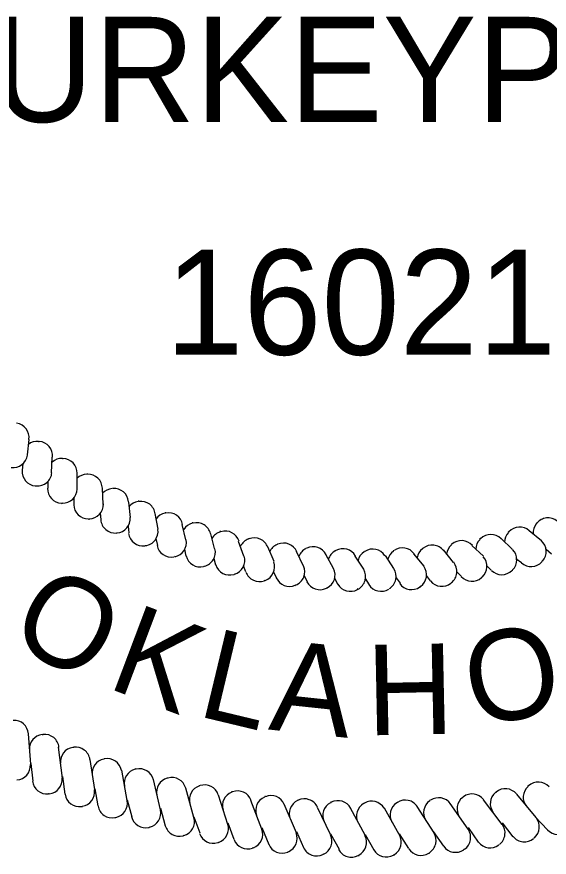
# Model space of a CAD drawing. Extents: x 2121385 to 2181200, y 132498 to 161273.
# Drawn here: x 2179786 to 2180417, y 136522 to 137518 of the extents above; entities that cross this region are included whole.
import ezdxf

# ---------------------------------------------------------------- set-up
doc = ezdxf.new("R2010")
doc.units = 0
doc.layers.add('SHT_Stamp_PE', color=7, linetype='Continuous')

msp = doc.modelspace()

# ---------------------------------------------------------------- linework, layer by layer
at = {"layer": 'SHT_Stamp_PE'}
for p, q in [((2179798.47, 136998.78), (2179800.31, 137017.12)), ((2179812.22, 137014.37), (2179811.31, 137014.37)), ((2179826.89, 136977.7), (2179827.81, 136996.03)), ((2179792.97, 136988.7), (2179792.06, 136980.45)), ((2179840.64, 136994.2), (2179839.72, 136994.2)), ((2179857.14, 136958.45), (2179857.14, 136976.78)), ((2179869.97, 136975.87), (2179869.06, 136975.87)), ((2179822.31, 136967.62), (2179822.31, 136959.37)), ((2179807.64, 136962.12), (2179808.56, 136962.12)), ((2179888.31, 136940.12), (2179887.39, 136959.37)), ((2179899.31, 136958.45), (2179899.31, 136958.45)), ((2179853.47, 136947.45), (2179853.47, 136939.2)), ((2179838.81, 136941.03), (2179839.72, 136941.95)), ((2179920.39, 136924.53), (2179918.56, 136942.87)), ((2179930.47, 136943.78), (2179929.56, 136943.78)), ((2179884.64, 136930.03), (2179885.56, 136921.78)), ((2179953.39, 136910.78), (2179949.72, 136929.12)), ((2179962.56, 136930.03), (2179961.64, 136930.03)), ((2179870.89, 136922.7), (2179871.81, 136922.7)), ((2179986.39, 136897.95), (2179981.81, 136916.28)), ((2179994.64, 136918.12), (2179993.72, 136918.12)), ((2180402.56, 136918.12), (2180401.64, 136917.2)), ((2179903.89, 136906.2), (2179904.81, 136906.2)), ((2179917.64, 136914.45), (2179918.56, 136906.2)), ((2180027.64, 136908.03), (2180026.72, 136908.03)), ((2180369.56, 136908.03), (2180368.64, 136907.12)), ((2180408.06, 136897.03), (2180393.39, 136908.95)), ((2179950.64, 136899.78), (2179952.47, 136891.53)), ((2180020.31, 136887.87), (2180015.72, 136905.28)), ((2180055.14, 136878.7), (2180048.72, 136896.12)), ((2180061.56, 136899.78), (2180060.64, 136898.87)), ((2180335.64, 136899.78), (2180334.72, 136898.87)), ((2180373.22, 136886.95), (2180360.39, 136899.78)), ((2179937.81, 136891.53), (2179938.72, 136891.53)), ((2179984.56, 136886.95), (2179986.39, 136878.7)), ((2180090.89, 136872.28), (2180083.56, 136889.7)), ((2180095.47, 136893.37), (2180094.56, 136892.45)), ((2180129.39, 136887.87), (2180128.47, 136887.87)), ((2180267.81, 136887.87), (2180266.89, 136887.87)), ((2180303.56, 136871.37), (2180291.64, 136886.03)), ((2180301.72, 136893.37), (2180300.81, 136892.45)), ((2180339.31, 136878.7), (2180325.56, 136891.53)), ((2180413.56, 136886.95), (2180419.97, 136881.45)), ((2179972.64, 136877.78), (2179973.56, 136878.7)), ((2180019.39, 136875.95), (2180021.22, 136868.62)), ((2180125.72, 136866.78), (2180117.47, 136884.2)), ((2180161.47, 136864.03), (2180152.31, 136880.53)), ((2180164.22, 136885.12), (2180163.31, 136885.12)), ((2180197.22, 136863.12), (2180187.14, 136878.7)), ((2180199.06, 136884.2), (2180198.14, 136884.2)), ((2180232.97, 136864.03), (2180222.89, 136879.62)), ((2180232.97, 136885.12), (2180232.06, 136885.12)), ((2180268.72, 136866.78), (2180256.81, 136881.45)), ((2180377.81, 136875.95), (2180384.22, 136871.37)), ((2180007.47, 136866.78), (2180008.39, 136866.78)), ((2180054.22, 136867.7), (2180056.97, 136860.37)), ((2180342.97, 136867.7), (2180348.47, 136862.2)), ((2180408.97, 136872.28), (2180408.97, 136873.2)), ((2180043.22, 136856.7), (2180044.14, 136857.62)), ((2180089.97, 136860.37), (2180093.64, 136853.03)), ((2180126.64, 136855.78), (2180130.31, 136848.45)), ((2180271.47, 136855.78), (2180276.06, 136849.37)), ((2180307.22, 136860.37), (2180312.72, 136854.87)), ((2180373.22, 136862.2), (2180374.14, 136862.2)), ((2180078.97, 136849.37), (2180079.89, 136850.28)), ((2180162.39, 136853.03), (2180166.06, 136845.7)), ((2180199.06, 136852.12), (2180203.64, 136844.78)), ((2180235.72, 136853.03), (2180240.31, 136846.62)), ((2180300.81, 136846.62), (2180301.72, 136847.53)), ((2180336.56, 136853.03), (2180337.47, 136853.95)), ((2180115.64, 136843.87), (2180116.56, 136844.78)), ((2180153.22, 136841.12), (2180154.14, 136841.12)), ((2180189.89, 136839.28), (2180190.81, 136840.2)), ((2180227.47, 136840.2), (2180227.47, 136840.2)), ((2180264.14, 136842.03), (2180265.06, 136842.95)), ((2179802.14, 136632.12), (2179799.39, 136667.87)), ((2179816.81, 136666.95), (2179815.89, 136666.95)), ((2179839.72, 136615.62), (2179835.14, 136652.28)), ((2179852.56, 136652.28), (2179852.56, 136651.37)), ((2179878.22, 136601.87), (2179872.72, 136637.62)), ((2179890.14, 136638.53), (2179889.22, 136638.53)), ((2179802.14, 136633.03), (2179804.89, 136611.95)), ((2179926.81, 136626.62), (2179925.89, 136625.7)), ((2179839.72, 136617.45), (2179842.47, 136596.37)), ((2179916.72, 136589.03), (2179910.31, 136624.78)), ((2179956.14, 136578.03), (2179947.89, 136613.78)), ((2179965.31, 136615.62), (2179964.39, 136615.62)), ((2179823.22, 136597.28), (2179824.14, 136597.28)), ((2179878.22, 136602.78), (2179881.89, 136582.62)), ((2179995.56, 136568.87), (2179986.39, 136603.7)), ((2180002.89, 136606.45), (2180001.97, 136606.45)), ((2180041.39, 136599.12), (2180040.47, 136599.12)), ((2180353.97, 136599.12), (2180353.97, 136598.2)), ((2180392.47, 136606.45), (2180391.56, 136605.53)), ((2179916.72, 136589.95), (2179922.22, 136569.78)), ((2180035.89, 136560.62), (2180024.89, 136595.45)), ((2180076.22, 136555.12), (2180063.39, 136589.03)), ((2180080.81, 136593.62), (2180079.89, 136593.62)), ((2180119.31, 136589.03), (2180118.39, 136589.03)), ((2180158.72, 136587.2), (2180157.81, 136586.28)), ((2180237.56, 136587.2), (2180236.64, 136586.28)), ((2180276.06, 136589.03), (2180275.14, 136589.03)), ((2180315.47, 136593.62), (2180314.56, 136592.7)), ((2180361.31, 136560.62), (2180339.31, 136589.95)), ((2180401.64, 136568.87), (2180378.72, 136596.37)), ((2179862.64, 136581.7), (2179863.56, 136581.7)), ((2179956.14, 136579.87), (2179961.64, 136558.78)), ((2180117.47, 136550.53), (2180102.81, 136584.45)), ((2180157.81, 136548.7), (2180142.22, 136580.78)), ((2180199.06, 136547.78), (2180181.64, 136579.87)), ((2180198.14, 136586.28), (2180197.22, 136585.37)), ((2180239.39, 136548.7), (2180221.97, 136579.87)), ((2180280.64, 136550.53), (2180260.47, 136581.7)), ((2180320.97, 136555.12), (2180299.89, 136585.37)), ((2179902.06, 136568.87), (2179902.97, 136568.87)), ((2179995.56, 136569.78), (2180002.89, 136550.53)), ((2180400.72, 136569.78), (2180415.39, 136554.2)), ((2179942.39, 136556.95), (2179943.31, 136557.87)), ((2180035.89, 136562.45), (2180043.22, 136543.2)), ((2180076.22, 136556.95), (2180084.47, 136536.78)), ((2180320.97, 136556.95), (2180332.89, 136539.53)), ((2180361.31, 136562.45), (2180374.14, 136545.95)), ((2179982.72, 136546.87), (2179983.64, 136547.78)), ((2180117.47, 136552.37), (2180125.72, 136533.12)), ((2180157.81, 136549.62), (2180167.89, 136531.28)), ((2180199.06, 136548.7), (2180209.14, 136530.37)), ((2180239.39, 136549.62), (2180250.39, 136532.2)), ((2180279.72, 136552.37), (2180291.64, 136534.95)), ((2180023.97, 136538.62), (2180024.89, 136539.53)), ((2180398.89, 136544.12), (2180398.89, 136544.12)), ((2180065.22, 136533.12), (2180066.14, 136533.12)), ((2180107.39, 136527.62), (2180107.39, 136528.53)), ((2180315.47, 136530.37), (2180316.39, 136531.28)), ((2180357.64, 136536.78), (2180357.64, 136536.78)), ((2180148.64, 136524.87), (2180149.56, 136525.78)), ((2180190.81, 136523.95), (2180191.72, 136523.95)), ((2180232.97, 136523.95), (2180232.97, 136524.87)), ((2180274.22, 136526.7), (2180275.14, 136526.7))]:
    msp.add_line(p, q, dxfattribs=at)
for centre, start, end in [((2179783.12, 137019.42), 352.21112, 82.21112), ((2179810.03, 136997.73), 85.31452, 128.34659), ((2179810.98, 136997.65), 355.31452, 85.31452), ((2179781.31, 137000.87), 262.21112, 352.21112), ((2179839.02, 136977.45), 88.41792, 131.44999), ((2179839.98, 136977.42), 358.41792, 88.41792), ((2179809.23, 136979.1), 175.31452, 265.31452), ((2179810.18, 136979.03), 265.31452, 355.31452), ((2179869.07, 136958.76), 91.52132, 134.55339), ((2179870.03, 136958.79), 1.52132, 91.52132), ((2179839.23, 136958.81), 178.41792, 268.41792), ((2179840.18, 136958.78), 268.41792, 358.41792), ((2179900.09, 136941.74), 94.62472, 137.65679), ((2179901.04, 136941.81), 4.62472, 94.62472), ((2179870.29, 136940.16), 181.52132, 271.52132), ((2179871.24, 136940.19), 271.52132, 1.52132), ((2179931.98, 136926.41), 97.72812, 140.76019), ((2179932.93, 136926.54), 7.72812, 97.72812), ((2179964.66, 136912.84), 100.83152, 143.86359), ((2179965.59, 136913.02), 10.83152, 100.83152), ((2179902.31, 136923.23), 184.62472, 274.62472), ((2179903.26, 136923.3), 274.62472, 4.62472), ((2179998.02, 136901.05), 103.93492, 146.96699), ((2179998.94, 136901.28), 13.93492, 103.93492), ((2180415.2, 136906.26), 141.17572, 184.20779), ((2180415.8, 136907), 51.17572, 141.17572), ((2179935.2, 136908.05), 187.72812, 277.72812), ((2179936.14, 136908.18), 277.72812, 7.72812), ((2180031.97, 136891.09), 107.03832, 150.07039), ((2180032.88, 136891.37), 17.03832, 107.03832), ((2180381.51, 136895.45), 138.07232, 181.10439), ((2180382.15, 136896.16), 48.07232, 138.07232), ((2179969.8, 136894.86), 280.83152, 10.83152), ((2180066.41, 136882.98), 110.14172, 153.17379), ((2180067.31, 136883.31), 20.14172, 110.14172), ((2180313.33, 136880.02), 41.86552, 131.86552), ((2180347.28, 136886.48), 134.96892, 178.00099), ((2180347.96, 136887.16), 44.96892, 134.96892), ((2180396.48, 136884.25), 318.07232, 48.07232), ((2179968.86, 136894.68), 190.83152, 280.83152), ((2180004.13, 136883.37), 283.93492, 13.93492), ((2180101.24, 136876.74), 113.24512, 156.27719), ((2180102.12, 136877.12), 23.24512, 113.24512), ((2180136.36, 136872.41), 116.34852, 159.38059), ((2180137.21, 136872.83), 26.34852, 116.34852), ((2180172.49, 136870.44), 29.45192, 119.45192), ((2180207.84, 136869.97), 32.55532, 122.55532), ((2180243.17, 136871.41), 35.65872, 125.65872), ((2180277.62, 136874.17), 128.76212, 171.79419), ((2180278.36, 136874.77), 38.76212, 128.76212), ((2180312.62, 136879.38), 131.86552, 174.89759), ((2180361.63, 136874.49), 314.96892, 44.96892), ((2180003.2, 136883.15), 193.93492, 283.93492), ((2180039.03, 136873.77), 287.03832, 17.03832), ((2180171.66, 136869.97), 119.45192, 162.48399), ((2180207.04, 136869.46), 122.55532, 165.58739), ((2180242.39, 136870.86), 125.65872, 168.69079), ((2180326.29, 136866.63), 311.86552, 41.86552), ((2180038.12, 136873.49), 197.03832, 287.03832), ((2180074.4, 136866.07), 290.14172, 20.14172), ((2180110.13, 136860.29), 293.24512, 23.24512), ((2180254.61, 136856.7), 305.65872, 35.65872), ((2180290.59, 136860.69), 308.76212, 38.76212), ((2180395.85, 136883.54), 228.07232, 318.07232), ((2180073.5, 136865.74), 200.14172, 290.14172), ((2180146.12, 136856.46), 296.34852, 26.34852), ((2180182.27, 136854.58), 299.45192, 29.45192), ((2180218.47, 136854.66), 302.55532, 32.55532), ((2180360.95, 136873.81), 224.96892, 314.96892), ((2180109.25, 136859.91), 203.24512, 293.24512), ((2180145.27, 136856.03), 206.34852, 296.34852), ((2180253.84, 136856.14), 215.65872, 305.65872), ((2180289.84, 136860.1), 218.76212, 308.76212), ((2180325.58, 136865.99), 221.86552, 311.86552), ((2180181.44, 136854.11), 209.45192, 299.45192), ((2180217.67, 136854.15), 212.55532, 302.55532), ((2179782.41, 136666.9), 3.6, 93.6), ((2179817.68, 136650.13), 96, 183.38537), ((2179818.63, 136650.23), 6, 96), ((2179854.57, 136634.94), 98.4, 185.78537), ((2179855.52, 136635.08), 8.4, 98.4), ((2179892.07, 136621.31), 100.8, 188.18538), ((2179893, 136621.49), 10.8, 100.8), ((2179784.66, 136630.52), 273.6, 3.6), ((2179931.03, 136609.49), 13.2, 103.2), ((2179930.1, 136609.27), 103.2, 190.58537), ((2179821.45, 136613.87), 186, 276), ((2179822.4, 136613.97), 276, 6), ((2179968.61, 136598.83), 105.6, 192.98537), ((2179969.52, 136599.08), 15.6, 105.6), ((2180008.42, 136590.3), 18, 108), ((2180404.27, 136593.6), 42, 132), ((2179860.8, 136599.02), 278.4, 8.4), ((2180007.51, 136590.01), 108, 195.38538), ((2180046.76, 136582.83), 110.4, 197.78537), ((2180047.65, 136583.16), 20.4, 110.4), ((2180325.77, 136579.65), 37.2, 127.2), ((2180364.43, 136585.2), 129.6, 216.98538), ((2180365.17, 136585.81), 39.6, 129.6), ((2180403.57, 136592.97), 132, 219.38537), ((2179859.86, 136598.88), 188.4, 278.4), ((2179899.8, 136585.68), 280.8, 10.8), ((2180086.26, 136577.29), 112.8, 200.18538), ((2180087.14, 136577.66), 22.8, 112.8), ((2180125.97, 136573.42), 115.2, 202.58538), ((2180126.83, 136573.83), 25.2, 115.2), ((2180166.65, 136571.65), 27.6, 117.6), ((2180206.52, 136571.15), 30, 120), ((2180246.38, 136572.32), 32.4, 122.4), ((2180285.37, 136574.61), 124.8, 212.18537), ((2180286.15, 136575.15), 34.8, 124.8), ((2180325.01, 136579.08), 127.2, 214.58538), ((2179898.86, 136585.5), 190.8, 280.8), ((2179939.31, 136573.99), 283.2, 13.2), ((2180165.8, 136571.21), 117.6, 204.98538), ((2180205.69, 136570.67), 120, 207.38538), ((2180245.57, 136571.81), 122.4, 209.78537), ((2179938.39, 136573.78), 193.2, 283.2), ((2179979.29, 136563.97), 285.6, 15.6), ((2180388.37, 136557.7), 309.6, 39.6), ((2179978.37, 136563.71), 195.6, 285.6), ((2180019.64, 136555.63), 288, 18), ((2180347.78, 136550.6), 307.2, 37.2), ((2180018.74, 136555.33), 198, 288), ((2180060.32, 136548.98), 290.4, 20.4), ((2180101.23, 136544.05), 292.8, 22.8), ((2180142.32, 136540.83), 295.2, 25.2), ((2180183.5, 136539.34), 297.6, 27.6), ((2180224.71, 136539.57), 300, 30), ((2180265.87, 136541.52), 302.4, 32.4), ((2180306.92, 136545.2), 304.8, 34.8), ((2180427.92, 136565.85), 222, 312), ((2180059.42, 136548.65), 200.4, 290.4), ((2180100.35, 136543.68), 202.8, 292.8), ((2180347.02, 136550.02), 217.2, 307.2), ((2180387.64, 136557.09), 219.6, 309.6), ((2180141.45, 136540.42), 205.2, 295.2), ((2180182.66, 136538.89), 207.6, 297.6), ((2180223.88, 136539.09), 210, 300), ((2180265.07, 136541.01), 212.4, 302.4), ((2180306.14, 136544.66), 214.8, 304.8)]:
    msp.add_arc(centre, 17.14, start, end, dxfattribs=at)

# ---------------------------------------------------------------- texts
for s, p in [('PURKEYPILE', (2179645.4, 137393.62)), ('16021', (2179961.74, 137117.57))]:
    msp.add_text(s, height=124.675, dxfattribs=at).set_placement(p)
for s, height, rotation, p in [('O', 107.24, 331.10901, (2179772.18, 136779.66)), ('K', 107.24, 339.30976, (2179890.58, 136723.5)), ('L', 107.23, 346.50956, (2179997.55, 136689.83)), ('O', 107.24, 10.51184, (2180327.59, 136675.68)), ('A', 107.24, 353.93956, (2180083.28, 136673.26)), ('H', 107.24, 1.16247, (2180201.49, 136666.16))]:
    msp.add_text(s, height=height, rotation=rotation, dxfattribs=at).set_placement(p)

doc.saveas('drawing.dxf')
